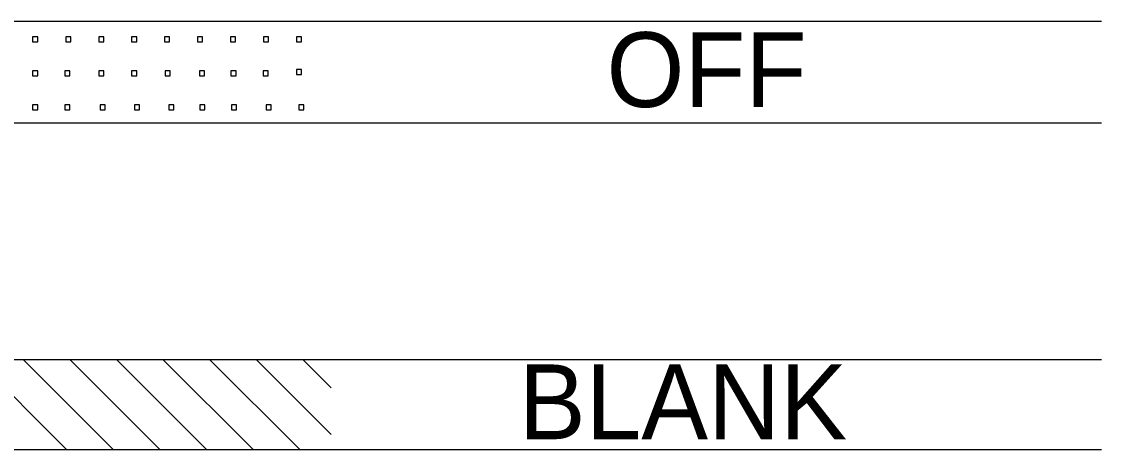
# Model space of a CAD drawing. Extents: x 10000 to 10825, y 10000 to 10530.
# Drawn here: x 10733.6 to 10784.1, y 10165.2 to 10185.2 of the extents above; entities that cross this region are included whole.
import ezdxf

# ---------------------------------------------------------------- set-up
doc = ezdxf.new("R2010")
doc.units = 0
doc.layers.add('Default', color=7, linetype='Continuous')
doc.layers.add('TextStructures', color=7, linetype='Continuous')

msp = doc.modelspace()

# ---------------------------------------------------------------- linework, layer by layer
at = {"layer": 'Default'}
for p, q in [((10784.11, 10185.22), (10490.187, 10185.22)), ((10490.187, 10180.482), (10784.11, 10180.482)), ((10490.187, 10169.414), (10784.11, 10169.414)), ((10735.847, 10169.414), (10740.061, 10165.202)), ((10738.027, 10169.414), (10742.242, 10165.202)), ((10740.208, 10169.414), (10744.422, 10165.202)), ((10742.388, 10169.414), (10746.603, 10165.202)), ((10744.569, 10169.414), (10748.084, 10165.901)), ((10746.749, 10169.414), (10748.084, 10168.08)), ((10490.187, 10165.202), (10784.11, 10165.202))]:
    msp.add_line(p, q, dxfattribs=at)
for points in [[(10734.347, 10184.267), (10734.347, 10184.507), (10734.11, 10184.506), (10734.11, 10184.267), (10734.347, 10184.267)], [(10734.347, 10184.267), (10734.347, 10184.507), (10734.11, 10184.506), (10734.11, 10184.267), (10734.347, 10184.267)], [(10735.895, 10184.267), (10735.895, 10184.507), (10735.658, 10184.506), (10735.658, 10184.267), (10735.895, 10184.267)], [(10737.437, 10184.267), (10737.437, 10184.507), (10737.2, 10184.506), (10737.2, 10184.267), (10737.437, 10184.267)], [(10738.978, 10184.267), (10738.978, 10184.507), (10738.742, 10184.506), (10738.742, 10184.267), (10738.978, 10184.267)], [(10740.52, 10184.267), (10740.52, 10184.507), (10740.284, 10184.506), (10740.284, 10184.267), (10740.52, 10184.267)], [(10742.062, 10184.267), (10742.062, 10184.507), (10741.825, 10184.506), (10741.825, 10184.267), (10742.062, 10184.267)], [(10743.604, 10184.267), (10743.604, 10184.507), (10743.367, 10184.506), (10743.367, 10184.267), (10743.604, 10184.267)], [(10745.146, 10184.267), (10745.146, 10184.507), (10744.909, 10184.506), (10744.909, 10184.267), (10745.146, 10184.267)], [(10746.687, 10184.267), (10746.687, 10184.507), (10746.451, 10184.506), (10746.451, 10184.267), (10746.687, 10184.267)], [(10746.687, 10182.746), (10746.687, 10182.986), (10746.451, 10182.985), (10746.451, 10182.746), (10746.687, 10182.746)], [(10734.347, 10182.679), (10734.347, 10182.919), (10734.11, 10182.918), (10734.11, 10182.679), (10734.347, 10182.679)], [(10734.347, 10182.679), (10734.347, 10182.919), (10734.11, 10182.918), (10734.11, 10182.679), (10734.347, 10182.679)], [(10735.852, 10182.679), (10735.852, 10182.919), (10735.615, 10182.918), (10735.615, 10182.679), (10735.852, 10182.679)], [(10737.437, 10182.679), (10737.437, 10182.919), (10737.2, 10182.918), (10737.2, 10182.679), (10737.437, 10182.679)], [(10738.978, 10182.679), (10738.978, 10182.919), (10738.742, 10182.918), (10738.742, 10182.679), (10738.978, 10182.679)], [(10740.542, 10182.679), (10740.542, 10182.919), (10740.305, 10182.918), (10740.305, 10182.679), (10740.542, 10182.679)], [(10742.148, 10182.679), (10742.148, 10182.919), (10741.911, 10182.918), (10741.911, 10182.679), (10742.148, 10182.679)], [(10743.625, 10182.679), (10743.625, 10182.919), (10743.389, 10182.918), (10743.389, 10182.679), (10743.625, 10182.679)], [(10745.124, 10182.679), (10745.124, 10182.919), (10744.888, 10182.918), (10744.888, 10182.679), (10745.124, 10182.679)], [(10734.347, 10181.091), (10734.347, 10181.331), (10734.11, 10181.329), (10734.11, 10181.091), (10734.347, 10181.091)], [(10734.347, 10181.091), (10734.347, 10181.331), (10734.11, 10181.329), (10734.11, 10181.091), (10734.347, 10181.091)], [(10735.852, 10181.091), (10735.852, 10181.331), (10735.615, 10181.329), (10735.615, 10181.091), (10735.852, 10181.091)], [(10737.501, 10181.091), (10737.501, 10181.331), (10737.264, 10181.329), (10737.264, 10181.091), (10737.501, 10181.091)], [(10739.107, 10181.091), (10739.107, 10181.331), (10738.87, 10181.329), (10738.87, 10181.091), (10739.107, 10181.091)], [(10740.713, 10181.091), (10740.713, 10181.331), (10740.476, 10181.329), (10740.476, 10181.091), (10740.713, 10181.091)], [(10742.169, 10181.091), (10742.169, 10181.331), (10741.932, 10181.329), (10741.932, 10181.091), (10742.169, 10181.091)], [(10743.647, 10181.091), (10743.647, 10181.331), (10743.41, 10181.329), (10743.41, 10181.091), (10743.647, 10181.091)], [(10745.274, 10181.091), (10745.274, 10181.331), (10745.037, 10181.329), (10745.037, 10181.091), (10745.274, 10181.091)], [(10746.795, 10181.091), (10746.795, 10181.331), (10746.558, 10181.329), (10746.558, 10181.091), (10746.795, 10181.091)], [(10731.487, 10169.414), (10735.701, 10165.202)], [(10733.667, 10169.414), (10737.881, 10165.202)], [(10735.846, 10169.414), (10735.876, 10169.385)]]:
    msp.add_lwpolyline(points, dxfattribs=at)

# ---------------------------------------------------------------- texts
at = {"layer": 'TextStructures'}
for s, p in [('OFF', (10760.96, 10181.222)), ('BLANK', (10756.86, 10165.679))]:
    msp.add_text(s, height=3.5, rotation=0.0007, dxfattribs=at).set_placement(p)

doc.saveas('drawing.dxf')
